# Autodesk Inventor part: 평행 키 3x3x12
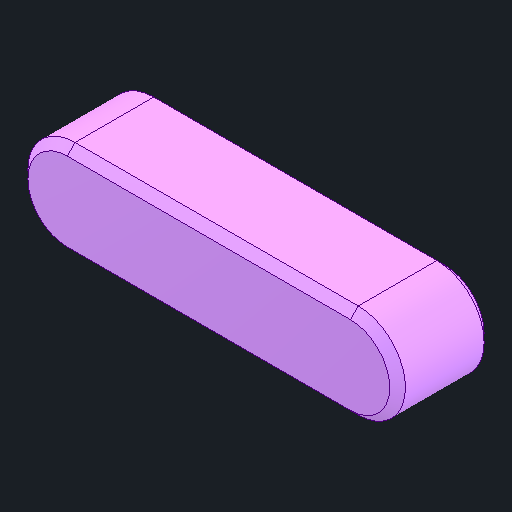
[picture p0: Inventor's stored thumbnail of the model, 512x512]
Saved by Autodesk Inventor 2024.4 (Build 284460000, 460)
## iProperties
Created: 2025-10
Part Number: 평행 키 3x3x12
Material: 강철, 연강
Description: 키 및 해당 키홈
Document SubType Name: Modeling
Designer: user
Density: 7.85 g/cm^3
Appearance: 기본값
Author: jhkim
Sending System: Autodesk Inventor 2026
Preprocessor: ST-DEVELOPER v20.1
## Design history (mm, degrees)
feature "Solid1"
node "솔리드1"
